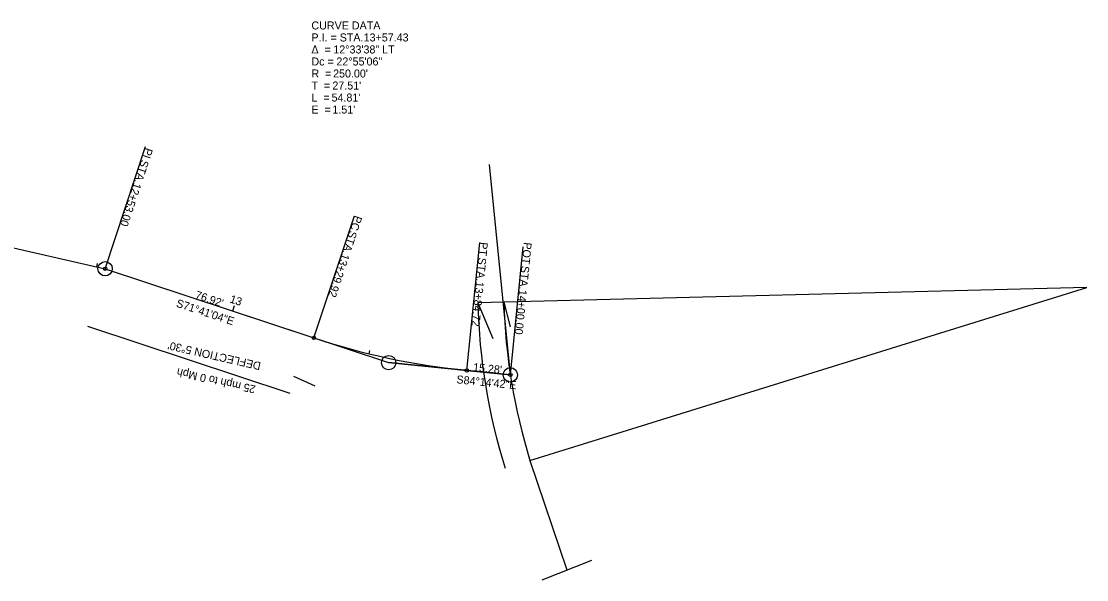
# Model space of a CAD drawing. Extents: x 1815851 to 1817341, y 427933 to 428286.
# Drawn here: x 1816968.4 to 1817341, y 427933.2 to 428128.4 of the extents above; entities that cross this region are included whole.
import ezdxf

# ---------------------------------------------------------------- set-up
doc = ezdxf.new("R2010")
doc.units = 0
for name, color, linetype in [('BR_P_Beam_Object', 7, 'Continuous'), ('BR_P_Rail_Object', 7, 'Continuous'), ('BR_P_Sub_Centerline', 7, 'Continuous'), ('Default', 7, 'Continuous'), ('DT_P_Graded_Shoulder', 7, 'Continuous'), ('PV_P_EOP', 7, 'Continuous'), ('RW_X_CL', 7, 'Continuous'), ('Z-EPARK', 7, 'Continuous'), ('Z-MEDIAN', 7, 'Continuous'), ('Z-PVMT-BRK', 7, 'Continuous')]:
    doc.layers.add(name, color=color, linetype=linetype)

msp = doc.modelspace()

# ---------------------------------------------------------------- linework, layer by layer
at = {"layer": 'BR_P_Rail_Object'}
for p, q in [((1816900.03, 428064.1), (1816997.7, 428041.88)), ((1816997.7, 428041.88), (1817070.72, 428017.71)), ((1817124.21, 428006.3), (1817139.41, 428004.77))]:
    msp.add_line(p, q, dxfattribs=at)
msp.add_arc((1817149.28, 428255.04), 250, 251.6844, 264.245, dxfattribs=at)
at = {"layer": 'BR_P_Sub_Centerline'}
for p, q in [((1816997.7, 428041.88), (1817096.84, 428009.06)), ((1817096.84, 428009.06), (1817139.41, 428004.77))]:
    msp.add_line(p, q, dxfattribs=at)
for centre in [(1817096.84, 428009.06), (1817139.41, 428004.77)]:
    msp.add_circle(centre, 2.5, dxfattribs=at)
msp.add_arc((1817149.28, 428255.04), 250, 251.6844, 264.245, dxfattribs=at)
at = {"layer": 'Default'}
for p, q in [((1817139.41, 428004.77), (1817132.13, 428078.38)), ((1816900.03, 428064.1), (1816997.7, 428041.88)), ((1816997.7, 428041.88), (1817096.84, 428009.06)), ((1817340.98, 428035.36), (1817128.04, 428030)), ((1817146.28, 427974.88), (1817340.98, 428035.36)), ((1817128.04, 428030), (1817133.33, 428017.48)), ((1817137.17, 428030.23), (1817139.32, 428021.53)), ((1817139.41, 428004.77), (1817096.84, 428009.06)), ((1817146.28, 427974.88), (1817159.22, 427936.56)), ((1817150.53, 427933.17), (1817167.91, 427939.95))]:
    msp.add_line(p, q, dxfattribs=at)
msp.add_circle((1816997.7, 428041.88), 2.5, dxfattribs=at)
for radius in [213.01, 203.88, 203.88]:
    msp.add_arc((1817340.98, 428035.36), radius, 181.4423, 197.2567, dxfattribs=at)
at = {"layer": 'DT_P_Graded_Shoulder'}
for p, q in [((1816991.51, 428021.81), (1817062.3, 427998.38)), ((1817063.63, 428004.29), (1817071.09, 428000.96))]:
    msp.add_line(p, q, dxfattribs=at)
at = {"layer": 'RW_X_CL'}
for p, q in [((1816997.7, 428041.88), (1817011.84, 428084.6)), ((1817070.72, 428017.71), (1817084.86, 428060.43)), ((1817124.21, 428006.3), (1817128.72, 428051.08)), ((1817139.41, 428004.77), (1817143.92, 428049.55))]:
    msp.add_line(p, q, dxfattribs=at)
for centre in [(1816997.7, 428041.88), (1817070.72, 428017.71), (1817124.21, 428006.3), (1817139.41, 428004.77)]:
    msp.add_circle(centre, 0.6, dxfattribs=at)
at = {"layer": 'Z-MEDIAN'}
for p, q in [((1816994.77, 428042.55), (1816995.04, 428043.72)), ((1817042.32, 428027.11), (1817042.94, 428029.01)), ((1817090.02, 428012.17), (1817090.3, 428013.34))]:
    msp.add_line(p, q, dxfattribs=at)

# ---------------------------------------------------------------- texts
at = {"layer": 'BR_P_Beam_Object'}
for s, rotation, p in [('S71°41\'04"E', 341.6844, (1817022.31, 428028.68)), ('S84°14\'42"E', 354.245, (1817120.45, 428001.86))]:
    msp.add_text(s, height=2.8, rotation=rotation, dxfattribs=at).set_placement(p)
at = {"layer": 'PV_P_EOP'}
for s, p in [("DEFLECTION 5°30'", (1817052.37, 428009.13)), ('25 mph to 0 Mph', (1817050.51, 428000.94))]:
    msp.add_text(s, height=2.8, rotation=167.1844, dxfattribs=at).set_placement(p)
at = {"layer": 'RW_X_CL'}
for s, rotation, p in [('PI', 251.6844, (1817011.81, 428084.38)), (' STA. ', 251.6844, (1817010.74, 428081.16)), ('12+53.00', 251.6844, (1817007.77, 428072.18)), ('PC', 251.6844, (1817085, 428060.71)), (' STA. ', 251.6844, (1817083.55, 428056.36)), ('PT', 264.245, (1817128.79, 428051.29)), ('POT', 264.245, (1817144.13, 428051.22)), ('13+29.92', 251.6844, (1817080.58, 428047.38)), (' STA. ', 264.245, (1817128.35, 428046.9)), (' STA. ', 264.245, (1817143.41, 428044.05)), ('13+84.72', 264.245, (1817127.4, 428037.5)), ('14+00.00', 264.245, (1817142.46, 428034.65))]:
    msp.add_text(s, height=2.8, rotation=rotation, dxfattribs=at).set_placement(p)
at = {"layer": 'Z-EPARK'}
for s, p in [('CURVE DATA', (1817069.84, 428125.55)), ('P.I. = STA. ', (1817069.84, 428121.35)), ('13+57.43', (1817088.1, 428121.35)), ('Δ  = ', (1817069.84, 428117.15)), ('12°33\'38" LT', (1817077.51, 428117.15)), ('Dc = ', (1817069.84, 428112.95)), ('22°55\'06"', (1817078.58, 428112.95)), ('R  = ', (1817069.84, 428108.75)), ("250.00'", (1817077.42, 428108.75)), ('T  = ', (1817069.84, 428104.55)), ("27.51'", (1817077.17, 428104.55)), ('L  = ', (1817069.84, 428100.35)), ("54.81'", (1817076.88, 428100.35)), ('E  = ', (1817069.84, 428096.15)), ("1.51'", (1817077.18, 428096.15))]:
    msp.add_text(s, height=2.8, dxfattribs=at).set_placement(p)
at = {"layer": 'Z-MEDIAN'}
msp.add_text('13', height=2.8, rotation=341.6844, dxfattribs=at).set_placement((1817041.06, 428030.16))
at = {"layer": 'Z-PVMT-BRK'}
for s, rotation, p in [("76.92'", 341.6844, (1817028.94, 428031.58)), ("15.28'", 354.245, (1817126.28, 428006.14))]:
    msp.add_text(s, height=2.8, rotation=rotation, dxfattribs=at).set_placement(p)

doc.saveas('drawing.dxf')
